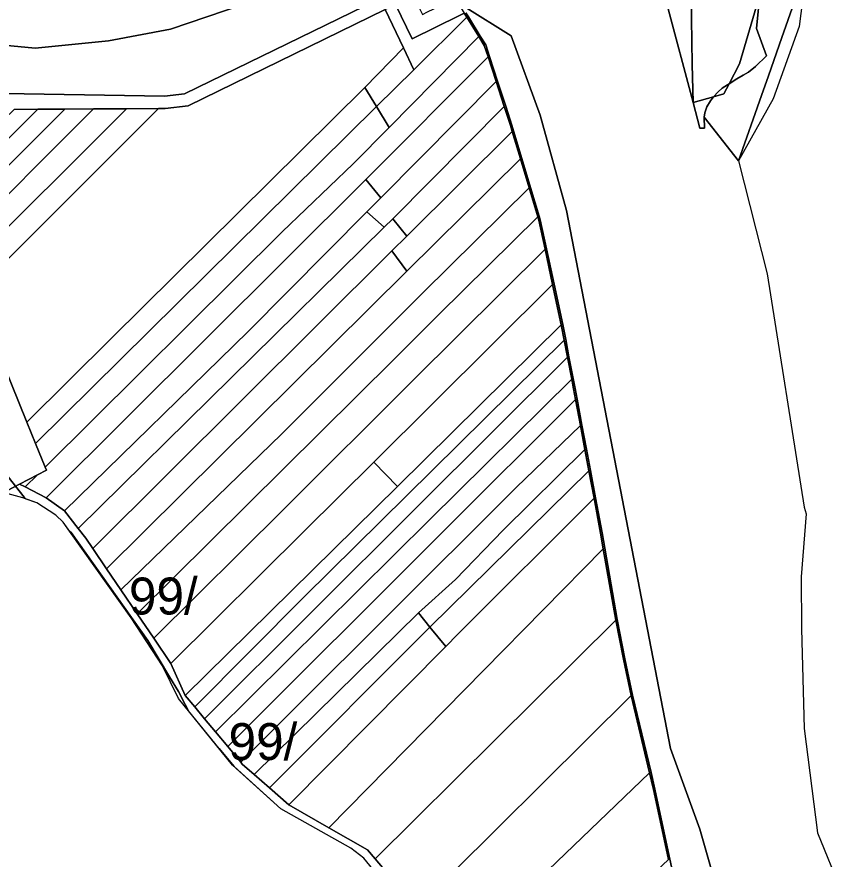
# Model space of a CAD drawing. Extents: x -535894 to -532827, y -1165802 to -1163635.
# Drawn here: x -533298.8 to -532964.2, y -1165246.7 to -1164904.6 of the extents above; entities that cross this region are included whole.
import ezdxf

# ---------------------------------------------------------------- set-up
doc = ezdxf.new("R2010")
doc.units = 0
for name, color, linetype in [('BPEJ_s', 7, 'Continuous'), ('orna_s', 7, 'Continuous'), ('ostatni_s', 7, 'Continuous'), ('trav_porost_s', 7, 'Continuous'), ('voda_s', 7, 'Continuous')]:
    doc.layers.add(name, color=color, linetype=linetype)

msp = doc.modelspace()

# ---------------------------------------------------------------- linework, layer by layer
at = {"layer": 'BPEJ_s'}
for points in [[(-532977.31, -1164877.84), (-532981.22, -1164908.52), (-532991.79, -1164937.99), (-533005.91, -1164963.1), (-532994.2, -1165009.04), (-532979.21, -1165103.79), (-532978.36, -1165106.4)], [(-533116.533, -1164902.995), (-533115.501, -1164904.659), (-533110.648, -1164912.493), (-533108.431, -1164916.081), (-533106.908, -1164920.756), (-533103.663, -1164930.745), (-533100.34, -1164940.944), (-533097.835, -1164948.637), (-533097.131, -1164950.989), (-533093.771, -1164962.208), (-533090.249, -1164973.968), (-533086.749, -1164985.636), (-533086.307, -1164987.103), (-533083.786, -1164998.813), (-533080.702, -1165013.15), (-533077.17, -1165029.609), (-533075.998, -1165035.716), (-533074.668, -1165042.665), (-533072.958, -1165051.547), (-533072.194, -1165055.526), (-533071.38, -1165059.872), (-533069.42, -1165070.392), (-533067.597, -1165080.142), (-533065.975, -1165088.803), (-533063.892, -1165099.931), (-533061.232, -1165114.191), (-533060.138, -1165120.449), (-533055.079, -1165149.423), (-533051.963, -1165165.364), (-533048.865, -1165180.125), (-533041.352, -1165211.535), (-533039.758, -1165218.191), (-533033.684, -1165246.624), (-533025.608, -1165284.384)], [(-533025.608, -1165284.384), (-533033.684, -1165246.624), (-533039.758, -1165218.191), (-533041.352, -1165211.535), (-533048.865, -1165180.125), (-533051.963, -1165165.364), (-533055.079, -1165149.423), (-533060.138, -1165120.449), (-533061.232, -1165114.191), (-533063.892, -1165099.931), (-533065.975, -1165088.803), (-533067.597, -1165080.142), (-533069.42, -1165070.392), (-533071.38, -1165059.872), (-533072.194, -1165055.526), (-533072.958, -1165051.547), (-533074.668, -1165042.665), (-533075.998, -1165035.716), (-533077.17, -1165029.609), (-533080.702, -1165013.15), (-533083.786, -1164998.813), (-533086.307, -1164987.103), (-533086.749, -1164985.636), (-533090.249, -1164973.968), (-533093.771, -1164962.208), (-533097.131, -1164950.989), (-533097.835, -1164948.637), (-533100.34, -1164940.944), (-533103.663, -1164930.745), (-533106.908, -1164920.756), (-533108.431, -1164916.081), (-533110.648, -1164912.493), (-533115.501, -1164904.659), (-533116.533, -1164902.995)], [(-533316.93, -1165073.03), (-533295.745, -1165099.748), (-533294.968, -1165100.432), (-533296.36, -1165099.92), (-533318.84, -1165093.8)], [(-533151.29, -1165254.43), (-533157.9, -1165246.26), (-533163.24, -1165242.28), (-533191.59, -1165226.21), (-533210.519, -1165209.105), (-533216.681, -1165201.753), (-533229.131, -1165186.444), (-533230.475, -1165183.857), (-533233.21, -1165178.59), (-533236.776, -1165172.663), (-533245.64, -1165157.93), (-533276.71, -1165113.99), (-533277.344, -1165113.547), (-533279.97, -1165109.85), (-533282.89, -1165106.98), (-533290.68, -1165102.01), (-533294.968, -1165100.432), (-533295.745, -1165099.748), (-533316.93, -1165073.03)], [(-532978.36, -1165106.4), (-532980.41, -1165132.1), (-532980.24, -1165153.13), (-532979.22, -1165193.65), (-532973.81, -1165236.01), (-532964.21, -1165259.48)]]:
    msp.add_lwpolyline(points, dxfattribs=at)
for points in [[(-533230.475, -1165183.857), (-533229.131, -1165186.444), (-533233.16, -1165181.49), (-533239.66, -1165168.21), (-533252.35, -1165148.73), (-533277.344, -1165113.547), (-533276.71, -1165113.99), (-533245.64, -1165157.93), (-533236.776, -1165172.663), (-533233.21, -1165178.59)], [(-533216.681, -1165201.753), (-533210.519, -1165209.105), (-533211.21, -1165208.48)]]:
    msp.add_lwpolyline(points, close=True, dxfattribs=at)
at = {"layer": 'orna_s'}
for points in [[(-533149.26, -1164901.65), (-533141.88, -1164917.25), (-533157.58, -1164933.38), (-533260.52, -1165035.2), (-533294.68, -1165069.27), (-533316.06, -1165016.63), (-533241.31, -1164941.86), (-533238.5, -1164941.84), (-533229.28, -1164940.77)], [(-533149.26, -1164901.65), (-533145.13, -1164899.63), (-533138.32, -1164913.61), (-533119.06, -1164904.11), (-533117.14, -1164903.15), (-533116.11, -1164904.82), (-533137.69, -1164926.13), (-533141.88, -1164917.25)], [(-533116.11, -1164904.82), (-533111.26, -1164912.65), (-533147.66, -1164949.6), (-533152.84, -1164941.12), (-533137.69, -1164926.13)], [(-533111.26, -1164912.65), (-533109.04, -1164916.24), (-533107.52, -1164920.92), (-533157.09, -1164970.71), (-533286.88, -1165099.92), (-533295.36, -1165095.55), (-533290.36, -1165090.63), (-533286.76, -1165088.76), (-533287.25, -1165087.56), (-533191.02, -1164991.97), (-533162.21, -1164964.36), (-533147.66, -1164949.6)], [(-533141.88, -1164917.25), (-533137.69, -1164926.13), (-533152.84, -1164941.12), (-533157.58, -1164933.38)], [(-533107.52, -1164920.92), (-533104.27, -1164930.9), (-533151.05, -1164978.13), (-533157.09, -1164970.71)], [(-533157.58, -1164933.38), (-533152.84, -1164941.12), (-533291.2, -1165077.84), (-533294.68, -1165069.27), (-533260.52, -1165035.2)], [(-533104.27, -1164930.9), (-533100.95, -1164941.1), (-533146.17, -1164986.67), (-533149.64, -1164990.09), (-533156.74, -1164983.77), (-533151.05, -1164978.13)], [(-533299.86, -1164942.25), (-533290.22, -1164942.19), (-533339.81, -1164991.22), (-533342.06, -1164992.28), (-533343.59, -1164984.36)], [(-533290.22, -1164942.19), (-533279.34, -1164942.12), (-533327.03, -1164989.6), (-533328.55, -1164985.88), (-533339.3, -1164990.98), (-533339.81, -1164991.22)], [(-533279.34, -1164942.12), (-533267.6, -1164942.04), (-533323.61, -1164998.03), (-533327.03, -1164989.6)], [(-533267.6, -1164942.04), (-533254.19, -1164941.95), (-533319.84, -1165007.34), (-533323.61, -1164998.03)], [(-533254.19, -1164941.95), (-533241.31, -1164941.86), (-533316.06, -1165016.63), (-533316.16, -1165016.4), (-533319.84, -1165007.34)], [(-533152.84, -1164941.12), (-533147.66, -1164949.6), (-533162.21, -1164964.36), (-533191.02, -1164991.97), (-533287.25, -1165087.56), (-533291.2, -1165077.84)], [(-533100.95, -1164941.1), (-533098.44, -1164948.8), (-533097.74, -1164951.15), (-533140.53, -1164993.73), (-533146.17, -1164986.67)], [(-533097.74, -1164951.15), (-533094.38, -1164962.37), (-533140.42, -1165007.98), (-533146.54, -1164999.72), (-533140.53, -1164993.73)], [(-533094.38, -1164962.37), (-533090.86, -1164974.13), (-533134.01, -1165016.65), (-533191.31, -1165074.15), (-533256.52, -1165137.33), (-533262.35, -1165128.75), (-533140.42, -1165007.98)], [(-533157.09, -1164970.71), (-533151.05, -1164978.13), (-533156.74, -1164983.77), (-533204.88, -1165032.37), (-533279.36, -1165105.17), (-533286.88, -1165099.92)], [(-533090.86, -1164974.13), (-533087.36, -1164985.79), (-533127.44, -1165025.54), (-533145.8, -1165043.76), (-533249.93, -1165147.04), (-533256.52, -1165137.33), (-533191.31, -1165074.15), (-533134.01, -1165016.65)], [(-533156.74, -1164983.77), (-533149.64, -1164990.09), (-533273.82, -1165112.38), (-533279.36, -1165105.17), (-533204.88, -1165032.37)], [(-533149.64, -1164990.09), (-533146.17, -1164986.67), (-533140.53, -1164993.73), (-533146.54, -1164999.72), (-533267.92, -1165120.55), (-533270.77, -1165116.36), (-533273.82, -1165112.38)], [(-533087.36, -1164985.79), (-533086.92, -1164987.26), (-533084.4, -1164998.97), (-533137.64, -1165051.96), (-533190.56, -1165104.63), (-533243.17, -1165156.99), (-533249.93, -1165147.04), (-533145.8, -1165043.76), (-533127.44, -1165025.54)], [(-533140.42, -1165007.98), (-533262.35, -1165128.75), (-533267.92, -1165120.55), (-533146.54, -1164999.72)], [(-533084.4, -1164998.97), (-533081.32, -1165013.31), (-533153.89, -1165085.42), (-533182.06, -1165113.41), (-533236.25, -1165167.26), (-533243.17, -1165156.99), (-533190.56, -1165104.63), (-533137.64, -1165051.96)], [(-533081.32, -1165013.31), (-533077.78, -1165029.77), (-533144.31, -1165095.36), (-533153.89, -1165085.42)], [(-533077.78, -1165029.77), (-533076.61, -1165035.87), (-533140.65, -1165099.16), (-533182.05, -1165140.09), (-533226.46, -1165184.88), (-533230.42, -1165180.24), (-533144.31, -1165095.36)], [(-533144.31, -1165095.36), (-533230.42, -1165180.24), (-533236.25, -1165167.26), (-533182.06, -1165113.41), (-533153.89, -1165085.42)], [(-533290.36, -1165090.63), (-533295.36, -1165095.55), (-533297.64, -1165094.39)]]:
    msp.add_lwpolyline(points, close=True, dxfattribs=at)
at = {"layer": 'ostatni_s'}
for points in [[(-533013.9, -1164850.14), (-533013.81, -1164850.1), (-533010.63, -1164859.43), (-533010.45, -1164859.97), (-533010.66, -1164860.03), (-533003.87, -1164880.13), (-532999.62, -1164888.13), (-532997.96, -1164892.84), (-532998.67, -1164900.76), (-533005.49, -1164923.73), (-533009.67, -1164931.84), (-533010.36, -1164932.29), (-533012.47, -1164933.65), (-533014.17, -1164935.04), (-533016.06, -1164937.15), (-533024.33, -1164939.46), (-533024.62, -1164923.92), (-533025.13, -1164896.12), (-533015.73, -1164893.02), (-533017.56, -1164884.6), (-533021.51, -1164873.18), (-533018.63, -1164862.11), (-533016.75, -1164854.92), (-533014.78, -1164845.11)], [(-533122.04, -1164897.68), (-533119.37, -1164896.37), (-533119.82, -1164898.82), (-533117.14, -1164903.15), (-533119.06, -1164904.11), (-533138.32, -1164913.61), (-533145.13, -1164899.63), (-533137.86, -1164896.07), (-533136.13, -1164899.58), (-533135.74, -1164900.39), (-533134.16, -1164903.63), (-533132.1, -1164902.62)], [(-532997.96, -1164892.84), (-532997.55, -1164893.98), (-532997.02, -1164894.02), (-532998.63, -1164909.37), (-532994.46, -1164920.43), (-532998.95, -1164924.85), (-533001.85, -1164927.06), (-533003.92, -1164928.32), (-533006.56, -1164929.76), (-533009.67, -1164931.84), (-533005.49, -1164923.73), (-532998.67, -1164900.76)], [(-533035.02, -1164899.39), (-533025.13, -1164896.12), (-533024.62, -1164923.92), (-533024.33, -1164939.46)], [(-533009.67, -1164931.84), (-533011.8, -1164935.96), (-533016.06, -1164937.15), (-533014.17, -1164935.04), (-533012.47, -1164933.65), (-533010.36, -1164932.29)], [(-533016.06, -1164937.15), (-533017.27, -1164938.72), (-533018.74, -1164941.21), (-533019.5, -1164943.61), (-533019.74, -1164945.35), (-533019.75, -1164945.44), (-533019.65, -1164949.83), (-533021.57, -1164949.83), (-533024.33, -1164939.46)], [(-533316.06, -1165016.63), (-533294.68, -1165069.27), (-533291.2, -1165077.84), (-533287.25, -1165087.56), (-533286.76, -1165088.76), (-533290.36, -1165090.63), (-533297.64, -1165094.39), (-533302.55, -1165096.94), (-533305.48, -1165090.39), (-533308.51, -1165083.67), (-533331.65, -1165032.22), (-533332.19, -1165031.01), (-533333.62, -1165022.99), (-533316.16, -1165016.4)]]:
    msp.add_lwpolyline(points, close=True, dxfattribs=at)
for points in [[(-533147.32, -1164895.13), (-533230.7, -1164935.9), (-533238.8, -1164936.84), (-533312.12, -1164935.66), (-533318.96, -1164935.26), (-533328.53, -1164937.19), (-533339.52, -1164934.29), (-533341.76, -1164933.66), (-533346.78, -1164932.24), (-533348.75, -1164931.67), (-533391.45, -1164912.18), (-533408.38, -1164903.25)], [(-533408.38, -1164903.25), (-533391.45, -1164912.18), (-533348.75, -1164931.67), (-533346.78, -1164932.24), (-533341.76, -1164933.66), (-533339.52, -1164934.29), (-533328.53, -1164937.19), (-533318.96, -1164935.26), (-533312.12, -1164935.66), (-533238.8, -1164936.84), (-533230.7, -1164935.9), (-533147.32, -1164895.13)], [(-533389.23, -1164897.67), (-533361.33, -1164907.54), (-533340.78, -1164912.67), (-533291.28, -1164917.31), (-533261.61, -1164914.36), (-533236.41, -1164909.7), (-533192.2, -1164894.47)], [(-533149.26, -1164901.65), (-533229.28, -1164940.77), (-533238.5, -1164941.84), (-533241.31, -1164941.86), (-533254.19, -1164941.95), (-533267.6, -1164942.04), (-533279.34, -1164942.12), (-533290.22, -1164942.19), (-533299.86, -1164942.25)], [(-533117.22, -1164900.45), (-533098.11, -1164912.42), (-533086.39, -1164944.59), (-533075.69, -1164983.34), (-533033.46, -1165201.68), (-533021.55, -1165234.47), (-533011.43, -1165270.01)], [(-533034.31, -1165246.78), (-533040.38, -1165218.35), (-533041.97, -1165211.69), (-533049.49, -1165180.28), (-533052.58, -1165165.52), (-533055.7, -1165149.58), (-533060.76, -1165120.61), (-533061.85, -1165114.35), (-533064.51, -1165100.09), (-533066.59, -1165088.96), (-533068.21, -1165080.3), (-533070.04, -1165070.55), (-533072, -1165060.03), (-533072.81, -1165055.68), (-533073.57, -1165051.71), (-533075.28, -1165042.82), (-533076.61, -1165035.87), (-533077.78, -1165029.77), (-533081.32, -1165013.31), (-533084.4, -1164998.97), (-533086.92, -1164987.26), (-533087.36, -1164985.79), (-533090.86, -1164974.13), (-533094.38, -1164962.37), (-533097.74, -1164951.15), (-533098.44, -1164948.8), (-533100.95, -1164941.1), (-533104.27, -1164930.9), (-533107.52, -1164920.92), (-533109.04, -1164916.24), (-533111.26, -1164912.65), (-533116.11, -1164904.82), (-533117.14, -1164903.15)], [(-533151.29, -1165254.43), (-533157.9, -1165246.26), (-533163.24, -1165242.28), (-533191.59, -1165226.21), (-533211.21, -1165208.48), (-533233.16, -1165181.49), (-533239.66, -1165168.21), (-533252.35, -1165148.73), (-533279.97, -1165109.85), (-533282.89, -1165106.98), (-533290.68, -1165102.01), (-533296.36, -1165099.92), (-533318.84, -1165093.8)], [(-533302.55, -1165096.94), (-533297.64, -1165094.39), (-533295.36, -1165095.55), (-533286.88, -1165099.92), (-533279.36, -1165105.17), (-533273.82, -1165112.38), (-533270.77, -1165116.36), (-533267.92, -1165120.55), (-533262.35, -1165128.75), (-533256.52, -1165137.33), (-533249.93, -1165147.04), (-533243.17, -1165156.99), (-533236.25, -1165167.26), (-533230.42, -1165180.24), (-533226.46, -1165184.88), (-533222.54, -1165189.63), (-533218.08, -1165195.01), (-533213.17, -1165200.95), (-533207.89, -1165207.35), (-533207.25, -1165208.12), (-533202.5, -1165212.26), (-533196.24, -1165217.73), (-533188.3, -1165224.67), (-533172.08, -1165233.95), (-533156.44, -1165242.91), (-533153.35, -1165246.57), (-533148.1, -1165252.82)]]:
    msp.add_lwpolyline(points, dxfattribs=at)
at = {"layer": 'trav_porost_s'}
for points in [[(-533076.61, -1165035.87), (-533075.28, -1165042.82), (-533136.31, -1165103.66), (-533222.54, -1165189.63), (-533226.46, -1165184.88), (-533182.05, -1165140.09), (-533140.65, -1165099.16)], [(-533075.28, -1165042.82), (-533073.57, -1165051.71), (-533131.26, -1165108.9), (-533218.08, -1165195.01), (-533222.54, -1165189.63), (-533136.31, -1165103.66)], [(-533073.57, -1165051.71), (-533072.81, -1165055.68), (-533072, -1165060.03), (-533126.21, -1165114.14), (-533213.17, -1165200.95), (-533218.08, -1165195.01), (-533131.26, -1165108.9)], [(-533072, -1165060.03), (-533070.04, -1165070.55), (-533096.16, -1165095.82), (-533120.47, -1165120.09), (-533125.29, -1165124.9), (-533207.89, -1165207.35), (-533213.17, -1165200.95), (-533126.21, -1165114.14)], [(-533070.04, -1165070.55), (-533068.21, -1165080.3), (-533101.38, -1165113.14), (-533120.76, -1165133.08), (-533135.8, -1165146.72), (-533202.5, -1165212.26), (-533207.25, -1165208.12), (-533207.89, -1165207.35), (-533125.29, -1165124.9), (-533120.47, -1165120.09), (-533096.16, -1165095.82)], [(-533068.21, -1165080.3), (-533066.59, -1165088.96), (-533131.14, -1165152.47), (-533135.8, -1165146.72), (-533120.76, -1165133.08), (-533101.38, -1165113.14)], [(-533066.59, -1165088.96), (-533064.51, -1165100.09), (-533119.77, -1165155.35), (-533124.7, -1165160.3), (-533131.14, -1165152.47)], [(-533064.51, -1165100.09), (-533061.85, -1165114.35), (-533060.76, -1165120.61), (-533109.26, -1165169.99), (-533172.08, -1165233.95), (-533188.3, -1165224.67), (-533124.7, -1165160.3), (-533119.77, -1165155.35)], [(-533060.76, -1165120.61), (-533055.7, -1165149.58), (-533153.35, -1165246.57), (-533156.44, -1165242.91), (-533172.08, -1165233.95), (-533109.26, -1165169.99)], [(-533131.14, -1165152.47), (-533196.24, -1165217.73), (-533202.5, -1165212.26), (-533135.8, -1165146.72)], [(-533124.7, -1165160.3), (-533188.3, -1165224.67), (-533196.24, -1165217.73), (-533131.14, -1165152.47)], [(-533055.7, -1165149.58), (-533052.58, -1165165.52), (-533049.49, -1165180.28), (-533139.66, -1165269.87), (-533140.71, -1165266.61), (-533148.1, -1165252.82), (-533153.35, -1165246.57)], [(-533049.49, -1165180.28), (-533041.97, -1165211.69), (-533127.5, -1165293.84), (-533133.87, -1165286.06), (-533136.9, -1165278.38), (-533139.66, -1165269.87)], [(-533041.97, -1165211.69), (-533040.38, -1165218.35), (-533034.31, -1165246.78), (-533108.53, -1165316.98), (-533127.5, -1165293.84)]]:
    msp.add_lwpolyline(points, close=True, dxfattribs=at)
at = {"layer": 'voda_s'}
msp.add_lwpolyline([(-532990.84, -1164820.26), (-532986.56, -1164818.1), (-532980.17, -1164845.09), (-532977.31, -1164877.84), (-532981.22, -1164908.52), (-532991.79, -1164937.99), (-533005.91, -1164963.1), (-532996.56, -1164936.58), (-532993.75, -1164928.6), (-532988.28, -1164913.08), (-532983.25, -1164898.77), (-532982.29, -1164880.52), (-532983.21, -1164860.62)], close=True, dxfattribs=at)
for points in [[(-533192.2, -1164894.47), (-533236.41, -1164909.7), (-533261.61, -1164914.36), (-533291.28, -1164917.31), (-533340.78, -1164912.67), (-533361.33, -1164907.54), (-533389.23, -1164897.67)], [(-532983.25, -1164898.77), (-532988.28, -1164913.08), (-532993.75, -1164928.6), (-532996.56, -1164936.58), (-533005.91, -1164963.1), (-533019.74, -1164945.35), (-533019.5, -1164943.61), (-533018.74, -1164941.21), (-533017.27, -1164938.72), (-533016.06, -1164937.15), (-533011.8, -1164935.96), (-533009.67, -1164931.84), (-533006.56, -1164929.76), (-533003.92, -1164928.32), (-533001.85, -1164927.06), (-532998.95, -1164924.85), (-532994.46, -1164920.43), (-532998.63, -1164909.37), (-532997.02, -1164894.02)], [(-533035.02, -1164899.39), (-533024.33, -1164939.46), (-533021.57, -1164949.83), (-533019.65, -1164949.83), (-533019.75, -1164945.44), (-533019.74, -1164945.35), (-533005.91, -1164963.1), (-532994.2, -1165009.04), (-532979.21, -1165103.79), (-532978.36, -1165106.4), (-532980.41, -1165132.1), (-532980.24, -1165153.13), (-532979.22, -1165193.65), (-532973.81, -1165236.01), (-532964.21, -1165259.48)], [(-533011.43, -1165270.01), (-533021.55, -1165234.47), (-533033.46, -1165201.68), (-533075.69, -1164983.34), (-533086.39, -1164944.59), (-533098.11, -1164912.42), (-533117.22, -1164900.45)]]:
    msp.add_lwpolyline(points, dxfattribs=at)

# ---------------------------------------------------------------- texts
at = {"layer": 'BPEJ_s'}
for p in [(-533253.238, -1165147.333), (-533212.803, -1165206.446)]:
    msp.add_text('99/', height=15, dxfattribs=at).set_placement(p)

doc.saveas('drawing.dxf')
